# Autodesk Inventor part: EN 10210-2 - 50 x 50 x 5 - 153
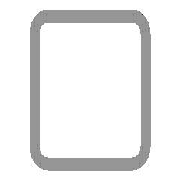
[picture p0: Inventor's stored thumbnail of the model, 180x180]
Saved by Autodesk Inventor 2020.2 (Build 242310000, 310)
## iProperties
_CCFamilyMember: 16
_CCFamilyDisplayName: DIN EN 10210-2 (USAS B17.1 quadratisch) - Rohrleitung — In Klammern angegebene Größen wurden aufgehoben
_FrameMemberDoc: Frame Member File
_Version: 15.0.0
_GetPNFromCC: 1
IsCustomPart: 1
Created: 2019-01
Part Number: EN 10210-2 - 50 x 50 x 5 - 153
Material: Stahl, weich
Description: Rohrleitung
Document SubType Name: Modeling
Standard: DIN
Designer: lutzd
Standard Revision: 2006-07
Standards Organization: DIN
Language: de-DE
Size Designation: 50 x 50 x 5
Categories: <MemberInstance><Categories><Category DisplayName="Profile" InternalName="089c4875-fa83-4c05-b084-43b9cc11f5ed" Mnemonic="GRDR"><CategoryParameter DisplayName="
Stock Number: 50 x 50 x 5
Mass: 1048.73 g
Surface Area: 535.429 cm^2
Volume: 133.596 cm^3
Density: 7.85 g/cm^3
Appearance: Semi-Polished(8)
G_L: 153,000 mm
G_W: 50,000 mm
G_H: 50,000 mm
+05482AED-7E95-40D3-ADFC-586D9B8C2141+SCHNITTDETAIL1: Schnittwinkel 90,00 grd
+66FE66A3-57D5-4BE4-88CE-EE3074938404+SCHNITTDETAIL2: Schnittwinkel 90,00 grd
DocNumber: ADSK-014331
Folder: .
Dimensions: 50x50x153 mm
Mass: 1,049 kg
VLT_Material: Stahl, weich
Title: Profil-Bauteil
Author: lutzd
Revision Number: -
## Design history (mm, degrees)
node "Startebene"
node "Endebene"
sketch "Skizze"
  geometry: L1 (-25, -17.5)-(-25, 17.5); L2 (-17.5, 25)-(17.5, 25); L3 (25, 17.5)-(25, -17.5); L4 (17.5, -25)-(-17.5, -25); L5 (-15, 20)-(15, 20); L6 (20, 15)-(20, -15); L7 (15, -20)-(-15, -20); L8 (-20, -15)-(-20, 15); L9 (0, 37.175)-(0, -37.175) reference; L10 (-37.175, 0)-(37.175, 0) reference; A1 r 7.5 centre (-17.5, -17.5) between (-25, -17.5) and (-17.5, -25); A2 r 7.5 centre (-17.5, 17.5) between (-17.5, 25) and (-25, 17.5); A3 r 7.5 centre (17.5, 17.5) between (25, 17.5) and (17.5, 25); A4 r 7.5 centre (17.5, -17.5) between (17.5, -25) and (25, -17.5); A5 r 5 centre (-15, -15) between (-20, -15) and (-15, -20); A6 r 5 centre (-15, 15) between (-15, 20) and (-20, 15); A7 r 5 centre (15, 15) between (20, 15) and (15, 20); A8 r 5 centre (15, -15) between (15, -20) and (20, -15)
  constraints: 16 end point, 16 point on circle, 16 tangent, 8 centre point, 6 equal radius, 4 parallel, 2 perpendicular, 2 other
  dimensions: "d7" = 7.5 radius of A1 (= G_IR); "d10" = 50 distance between parallel lines of L2 L4 (= G_H); "d11" = 50 distance between parallel lines of L1 L3 (= G_W); "d12" = 5 distance between parallel lines of L3 L6 (= G_T); "d15" = 25 distance between parallel lines of L2 L10 (= 0.5 x d10); "d16" = 25 distance between parallel lines of L9 L3 (= 0.5 x d11); "d19" = 5 radius of A5 (= G_T); "d20" = 5 distance between parallel lines of L4 L7 (= G_T)
extrude "Körper" new body sketch "Skizze" stored distance "d3" = 153 (= G_L); taper "d4" = 0 deg
node "Driven Length"
  sketch "Sketch3"
    geometry: L1 (0, 0)-(10, 0) reference
    constraints: 2 end point, 1 horizontal
  workplane "Work Plane3"
  sketch "Sketch4"
    geometry: L1 (-2, 50)-(12, 50) reference; L2 (-2, 203)-(12, 203) reference
    dimensions: "d18" = 153 distance between parallel lines of L1 L2 (derived)
workplane "Arbeitsebene4"
feature "Trennen1"
workplane "Arbeitsebene5"
feature "Trennen2"
body "Solid1"
other parameters: "G_W" = 50 [user parameter; used in 1 equation term], "G_H" = 50 [user parameter; used in 1 equation term], "G_T" = 5 [user parameter; used in 3 equation terms], "G_IR" = 7.5 [user parameter; used in 1 equation term], "G_L" = 153 (= d18) [user parameter; used in 1 equation term], "d14" = 203 (= G_OFFSET_END + B_L), "B_L" = 253 [user parameter; used in 1 equation term], "d17" = 90 deg
